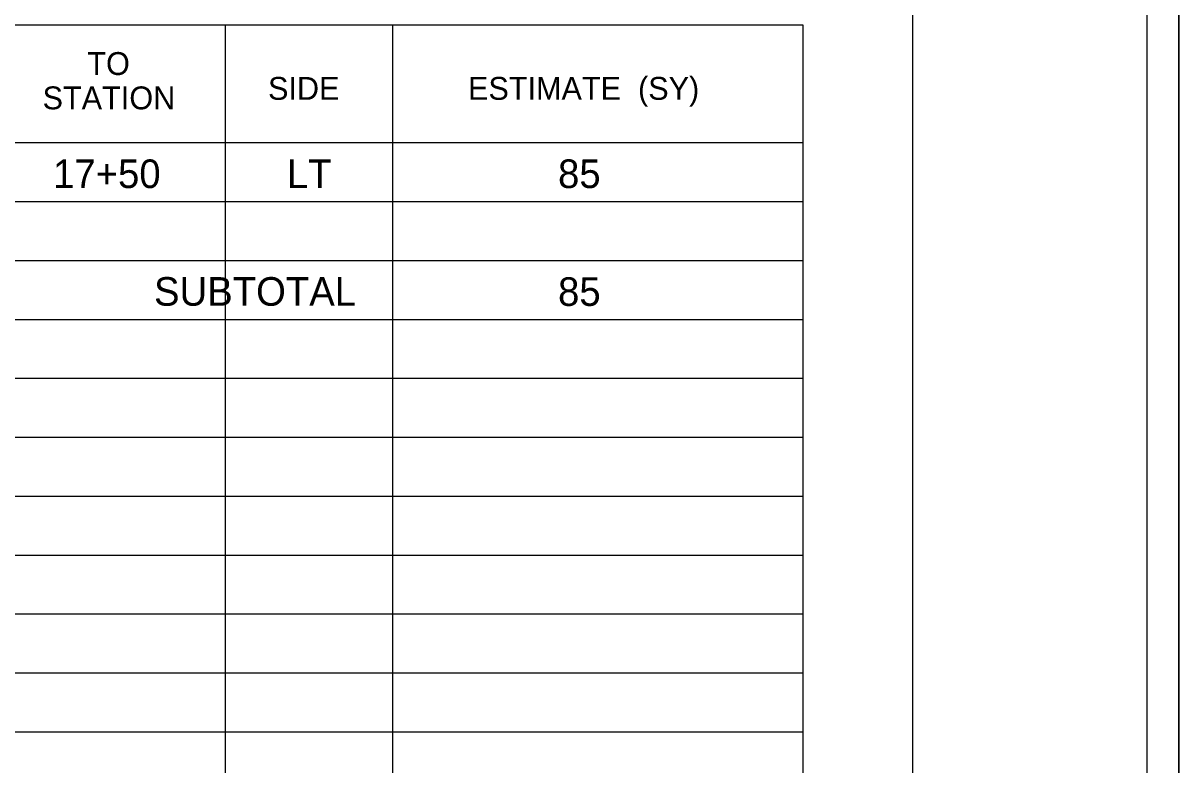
# Model space of a CAD drawing. Extents: x 1674550 to 1676250, y 1328139 to 1330492.
# Drawn here: x 1675756.8 to 1676249.8, y 1328689.5 to 1329006 of the extents above; entities that cross this region are included whole.
import ezdxf

# ---------------------------------------------------------------- set-up
doc = ezdxf.new("R2010")
doc.units = 0
for name, color, linetype in [('Matting Summary Sheet CELL', 7, 'Continuous'), ('Sheet Plan CELL', 7, 'Continuous'), ('Sheet Plot Border Outside CELL', 7, 'Continuous'), ('z - Construction', 7, 'Continuous')]:
    doc.layers.add(name, color=color, linetype=linetype)

msp = doc.modelspace()

# ---------------------------------------------------------------- linework, layer by layer
at = {"layer": 'Matting Summary Sheet CELL'}
for p, q in [((1675369.75, 1329005.32), (1676089.43, 1329005.32)), ((1675842.99, 1329005.32), (1675842.99, 1328200.91)), ((1675914.43, 1329005.32), (1675914.43, 1328200.9)), ((1675369.75, 1328955.04), (1676089.43, 1328955.04)), ((1675369.75, 1328929.9), (1676089.43, 1328929.9)), ((1675369.75, 1328904.77), (1676089.43, 1328904.77)), ((1675369.75, 1328879.63), (1676089.43, 1328879.63)), ((1675369.75, 1328854.49), (1676089.43, 1328854.49)), ((1675369.75, 1328829.35), (1676089.43, 1328829.35)), ((1675369.75, 1328804.21), (1676089.43, 1328804.21)), ((1675369.75, 1328779.08), (1676089.43, 1328779.08)), ((1675369.75, 1328753.94), (1676089.43, 1328753.94)), ((1675369.75, 1328728.8), (1676089.43, 1328728.8)), ((1675369.75, 1328703.66), (1676089.43, 1328703.66))]:
    msp.add_line(p, q, dxfattribs=at)
msp.add_lwpolyline([(1675369.75, 1329005.32), (1676089.43, 1329005.32), (1676089.43, 1328200.91), (1675369.75, 1328200.91)], close=True, dxfattribs=at)
at = {"layer": 'Sheet Plan CELL'}
for p, q in [((1676136.25, 1328161.42), (1676136.28, 1329216.4)), ((1676236.25, 1328161.42), (1676236.28, 1329216.4)), ((1676136.28, 1328980.29), (1676136.28, 1328980.29))]:
    msp.add_line(p, q, dxfattribs=at)
at = {"layer": 'Sheet Plot Border Outside CELL'}
msp.add_lwpolyline([(1674549.8, 1329238.9), (1676249.78, 1329238.9), (1676249.78, 1328138.92), (1674549.8, 1328138.92)], close=True, dxfattribs=at)
at = {"layer": 'z - Construction'}
msp.add_line((1676249.78, 1328138.92), (1676249.78, 1329238.9), dxfattribs=at)

# ---------------------------------------------------------------- texts
at = {"layer": 'Matting Summary Sheet CELL'}
for s, height, p in [('TO', 9.767, (1675784.2, 1328983.9)), ('SIDE', 9.763, (1675861.27, 1328973.31)), ('ESTIMATE  (SY)', 9.7626, (1675946.56, 1328973.31)), ('STATION', 9.767, (1675765.1, 1328969.25)), ('17+50', 12.209, (1675769.6, 1328935.66)), ('LT', 12.209, (1675869.32, 1328935.66)), ('85', 12.209, (1675984.98, 1328935.66)), ('SUBTOTAL', 12.209, (1675812.64, 1328885.45)), ('85', 12.209, (1675984.98, 1328885.38))]:
    msp.add_text(s, height=height, rotation=360, dxfattribs=at).set_placement(p)

doc.saveas('drawing.dxf')
